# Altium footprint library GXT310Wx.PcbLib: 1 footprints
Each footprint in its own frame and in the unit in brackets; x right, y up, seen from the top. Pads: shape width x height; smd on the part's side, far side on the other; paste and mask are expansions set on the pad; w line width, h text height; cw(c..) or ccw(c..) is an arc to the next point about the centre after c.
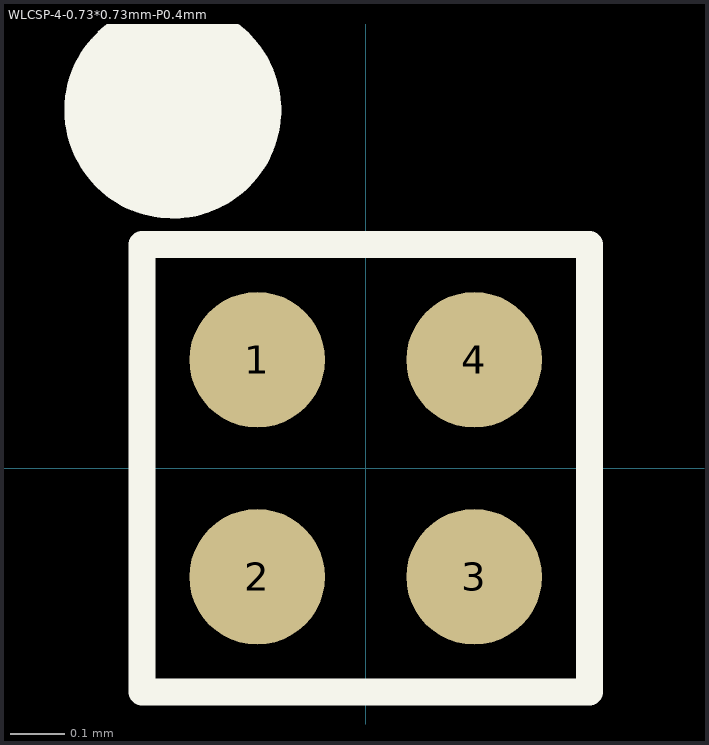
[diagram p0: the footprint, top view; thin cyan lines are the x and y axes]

## WLCSP-4-0.73*0.73mm-P0.4mm [mm]
height 0.55
pads (4):
  round 0.25 smd mask+0.05: 1(-0.2,0.2) 2(-0.2,-0.2) 3(0.2,-0.2) 4(0.2,0.2)
Top Overlay:
  circle w0.2: c-0.356,0.66 r0.1
  lines w0.05: -0.412,-0.412 0.413,-0.412 0.413,0.413 -0.412,0.413 -0.412,-0.412
3D body "WLCSP-4-0.73X0.73-P0.4.STEP": height 0.28, standoff 0, extent -0.331,-0.33 0.331,0.332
